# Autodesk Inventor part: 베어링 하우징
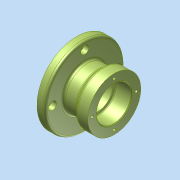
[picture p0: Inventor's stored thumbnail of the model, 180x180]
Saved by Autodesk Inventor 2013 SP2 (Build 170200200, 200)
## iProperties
Created: 2026-01
Part Number: 베어링 하우징
Material: Generic
Document SubType Name: Modeling
Designer: a
Density: 1 g/cm^3
Author: a
변환 표준: STEP AP214IS
전처리기: Build: 200, Release: 2013 SP2 Update 6 - Date: Thu 07/17/2014
전송 단위: 밀리미터
불확실성: 0.01
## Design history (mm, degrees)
node "베어링 하우징1"
node "솔리드1"
node "기준1"
